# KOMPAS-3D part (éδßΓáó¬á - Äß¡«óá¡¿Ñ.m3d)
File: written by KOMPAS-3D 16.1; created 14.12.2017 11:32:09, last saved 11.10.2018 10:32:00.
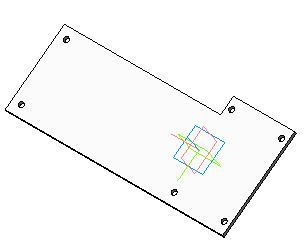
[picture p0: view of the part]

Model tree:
1. Эскиз:1
2. Операция выдавливания:1
     Расстояние 1 = 6
3. Эскиз:4
4. Вырезать элемент выдавливания:2
     Расстояние 1 = 6
5. Массив по сетке:1  (with: Вырезать элемент выдавливания:2, Эскиз:4)  (2 pattern instances)
     Наклон = 90; Шаг 1 = 102; Угол раствора = 90; Номер 1 = 1
6. Эскиз:5
7. Операция выдавливания:2
     Расстояние 1 = 144.5; Расстояние 2 = 6
8. Эскиз:6
9. Вырезать элемент выдавливания:3
     Расстояние 1 = 6
10. Эскиз:7
11. Операция выдавливания:3
     Расстояние 1 = 144.5; Расстояние 2 = 15
12. Скругление:1
     Радиус = 10
13. Фаска:2
     Угол = 45; Длина 1 = 1; Длина 2 = 1
14. Эскиз:2
15. Отверстие:1
     Глубина выреза = 15; Диаметр отверстия = 6; Угол конуса торца = 118; Координата X = -95; Координата Y = 12; Диаметр цековки/зенковки = 7.6; Глубина цековки = 8; Угол зенковки = 90
16. Эскиз:3
17. Вырезать элемент выдавливания:1
     Расстояние 1 = 15
18. Средняя плоскость:1
19. Зеркальный массив:1
20. Экземпляр ( 1 )
21. Экземпляр ( 2 )  (with: Вырезать элемент выдавливания:1)  (labels: Полипропилен  ГОСТ 26996-86)

Expressions: 26+3; 250+16
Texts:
  Body Specification ( left align )
  Body Specificaton ( centered )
